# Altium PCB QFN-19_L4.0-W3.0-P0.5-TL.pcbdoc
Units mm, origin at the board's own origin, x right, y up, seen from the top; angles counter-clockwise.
Board outline 16.63 x 17.43 mm, 2 copper layers (Top Layer, Bottom Layer), stack 0 mm thick; 1 components, 0 nets, 19 pads, 0 vias.
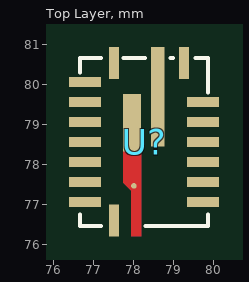
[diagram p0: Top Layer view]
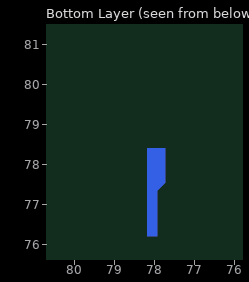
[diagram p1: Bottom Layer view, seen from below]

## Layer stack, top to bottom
Top Layer: signal copper (thickness not stored)
Bottom Layer: signal copper (thickness not stored)

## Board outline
86.484,69.85 69.85,69.85 69.85,87.282 86.484,87.282

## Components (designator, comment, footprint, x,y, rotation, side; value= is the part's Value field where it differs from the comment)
U? "" QFN-19_L4.0-W3.0-P0.5-TL 78.259,78.566 r0 top

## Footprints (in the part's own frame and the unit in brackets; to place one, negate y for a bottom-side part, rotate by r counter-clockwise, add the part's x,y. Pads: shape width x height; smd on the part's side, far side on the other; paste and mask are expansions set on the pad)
QFN-19_L4.0-W3.0-P0.5-TL [mm]
  rect 0.8x0.25 smd paste-100 mask+0.05: 1(-1.475,1.5) 2(-1.475,1) 3(-1.475,0.5) 4(-1.475,0) 5(-1.475,-0.5) 6(-1.475,-1) 7(-1.475,-1.5) 10(1.475,-1.5) 11(1.475,-1) 12(1.475,-0.5) 13(1.475,0) 14(1.475,0.5) 15(1.475,1)
  rect 0.25x0.8 smd paste-100 mask+0.05: 8(-0.75,-1.966) 16(1,1.966) 19(-0.75,1.966)
  round 0.138 smd: 9(-0.258,-1.102)
  rect 0.33x2.48 smd paste-100 mask+0.05: 17(0.34,1.126)
  rect 0.45x1.43 smd paste-100 mask+0.05: 18(-0.3,0.475)
  Top Layer region: -0.325,-2.365 -0.325,-1.23 -0.525,-1.03 -0.525,-0.16 -0.075,-0.16 -0.075,-2.365
  Bottom Layer region: -0.325,-2.365 -0.325,-1.23 -0.525,-1.03 -0.525,-0.16 -0.075,-0.16 -0.075,-2.365
  Multi-Layer region: -0.325,-2.365 -0.325,-1.23 -0.525,-1.03 -0.525,-0.16 -0.075,-0.16 -0.075,-2.365
  silkscreen extent -1.6,-2.1 1.6,2.1

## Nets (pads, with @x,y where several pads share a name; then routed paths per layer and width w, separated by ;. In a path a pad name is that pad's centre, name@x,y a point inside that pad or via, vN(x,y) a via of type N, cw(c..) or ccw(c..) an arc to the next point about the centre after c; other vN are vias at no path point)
pads on no net: U?.1 U?.2 U?.3 U?.4 U?.5 U?.6 U?.7 U?.8 U?.9 U?.10 U?.11 U?.12 U?.13 U?.14 U?.15 U?.16 U?.17 U?.18 U?.19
